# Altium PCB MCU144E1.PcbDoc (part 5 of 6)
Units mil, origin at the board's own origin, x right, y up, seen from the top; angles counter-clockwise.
Board outline 2755.9 x 2276.49 mil, 10 copper layers (Top Layer, L02_GND1, L03_SIG1, L04_GND2, L05_SIG2, L06_PWR, L07_GND3, L08_SIG3, L09_GND4, Bottom Layer), stack 60.4 mil thick; 257 components, 312 nets, 1297 pads, 831 vias.
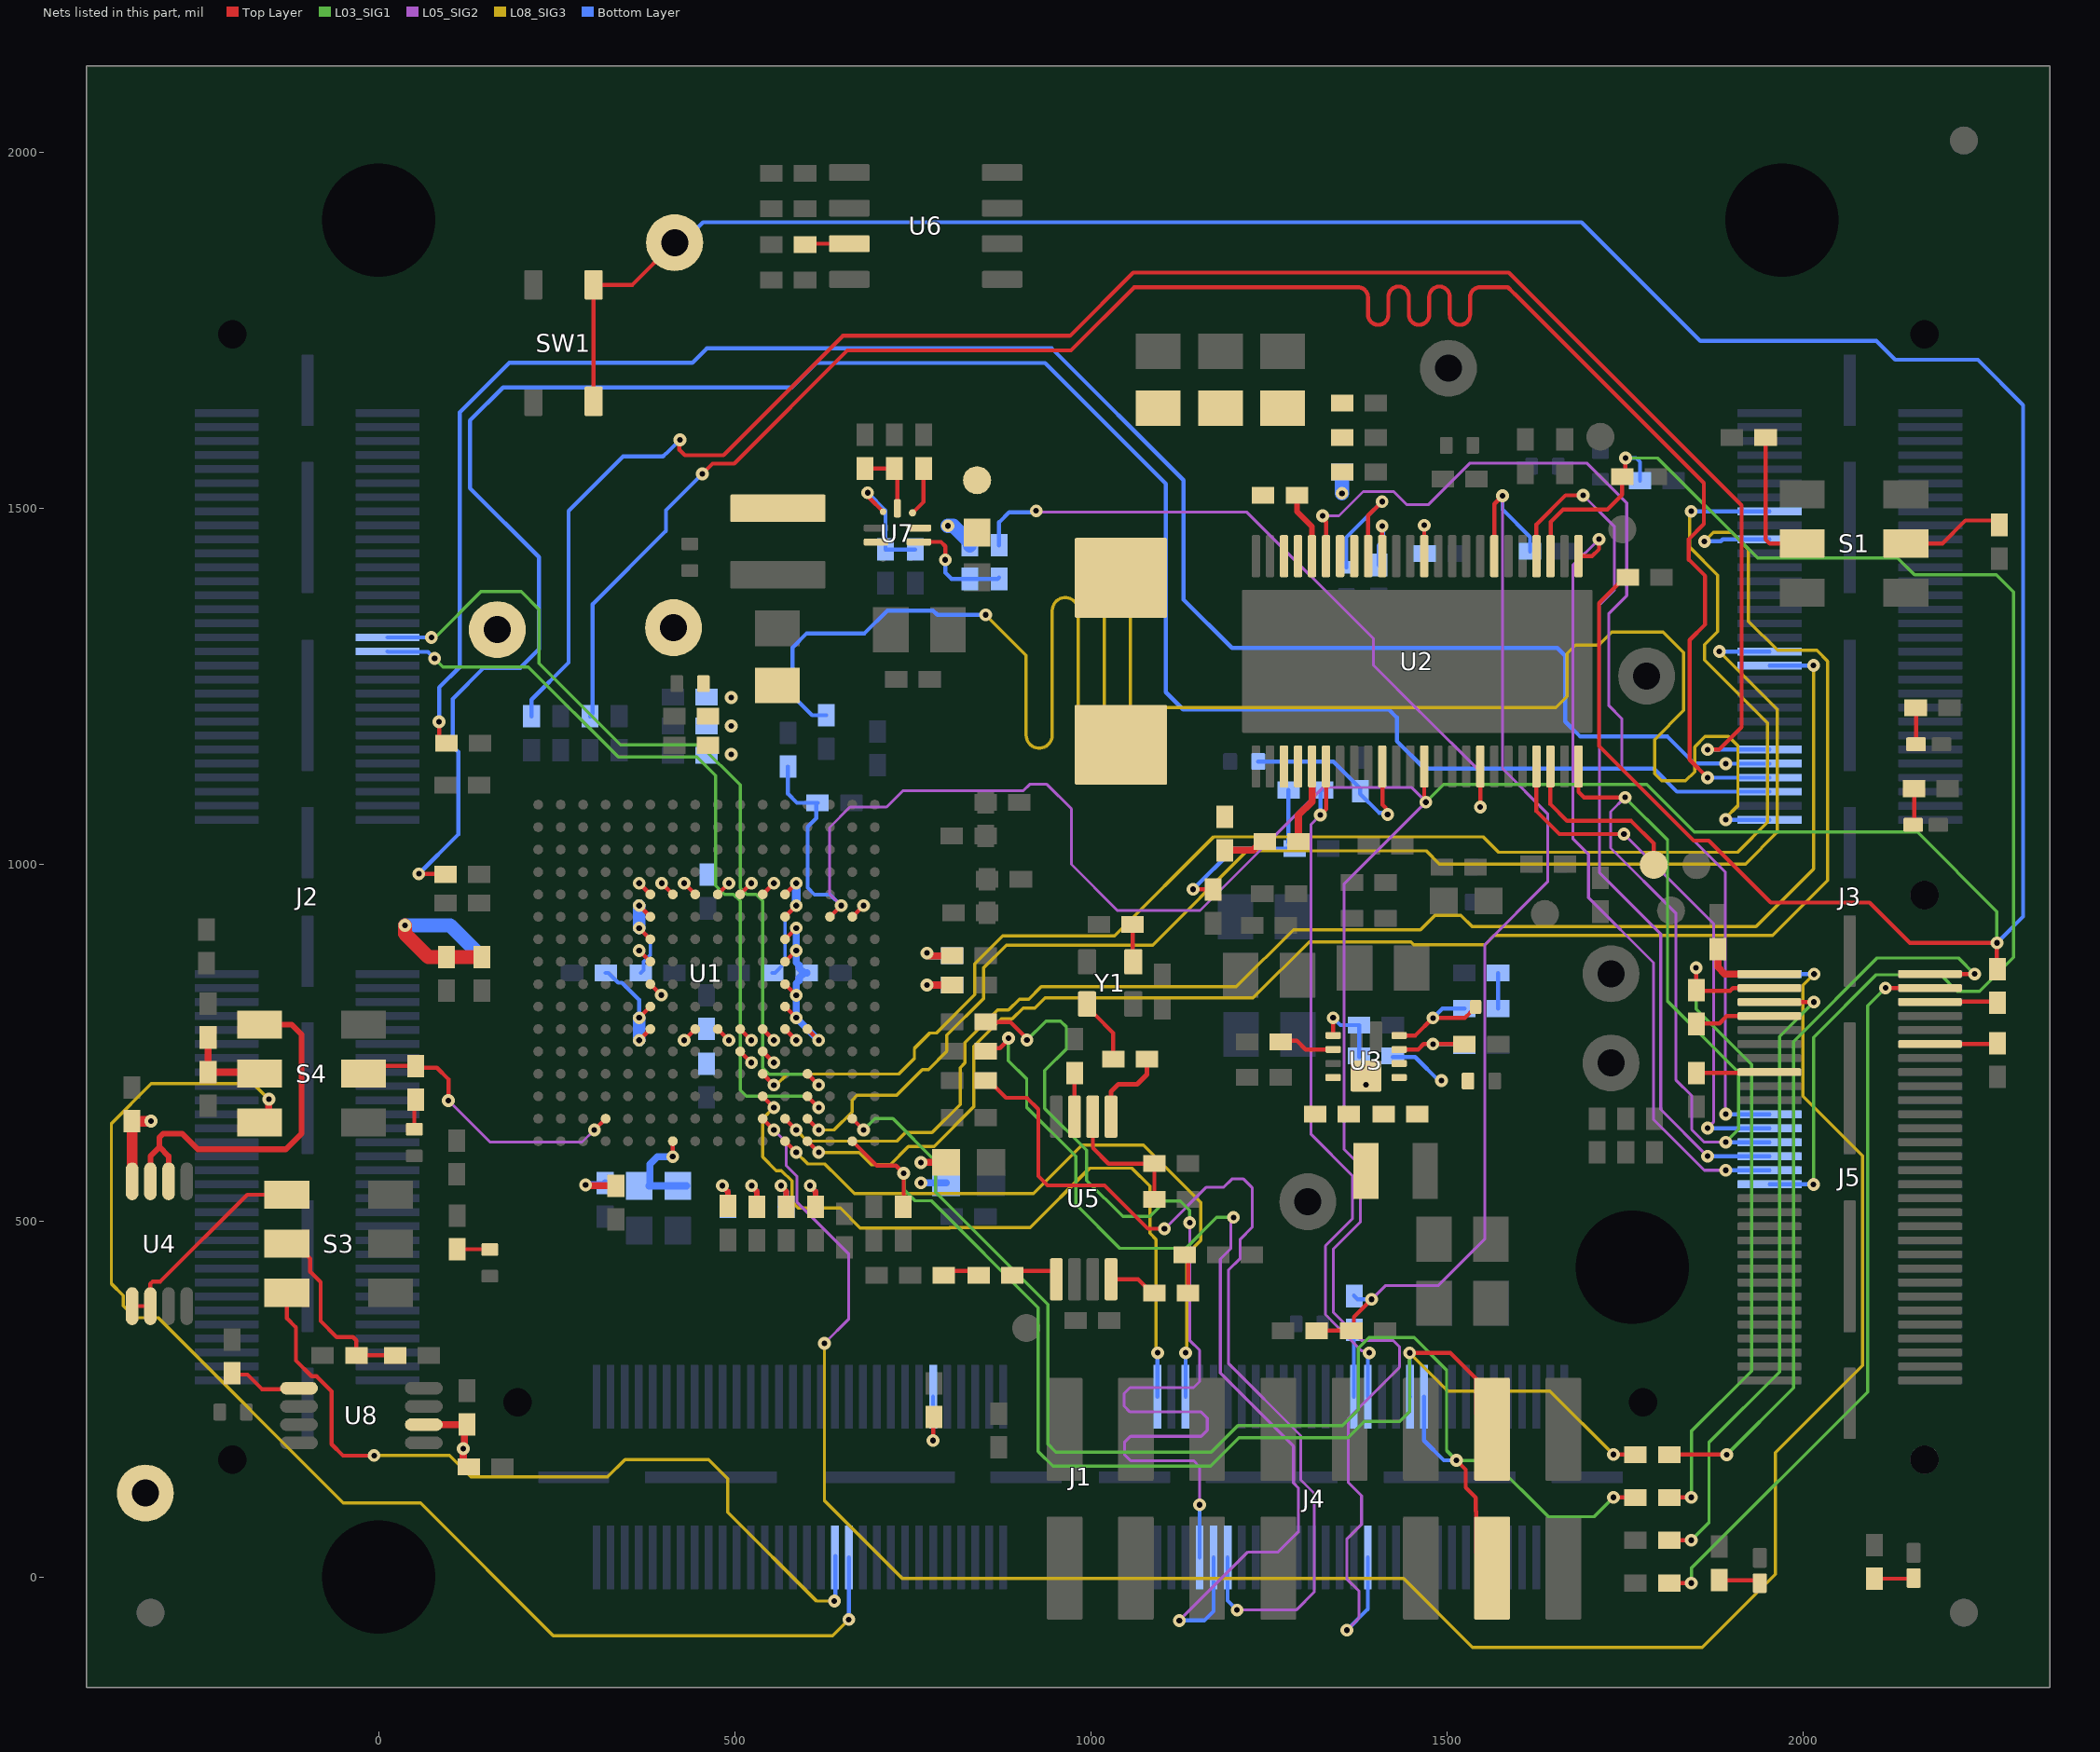
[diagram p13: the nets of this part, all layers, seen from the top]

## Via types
v1: diameter 18, hole 8, Top Layer to Bottom Layer, tented both sides, 777 vias
v2: diameter 19.68, hole 7.87, Top Layer to Bottom Layer, tented top, 54 vias

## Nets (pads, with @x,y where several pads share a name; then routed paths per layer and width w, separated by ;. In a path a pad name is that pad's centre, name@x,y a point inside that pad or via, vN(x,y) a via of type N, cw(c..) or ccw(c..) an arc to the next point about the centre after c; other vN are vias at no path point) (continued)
MCU_GPIO241: J3.105 U1.N11 | length 2233
  Top Layer w5.66: U1.N11@539,706.48 v1(554.75,690.73)
  L08_SIG3 w4.5: v1@556.92,692.91 v1(554.75,690.73) 558.08,690.73 573.61,706.27 730.27,706.27 752.02,728.02 752.02,742.21 773.6,763.79 782.94,763.79 836.86,817.71 836.86,860.77 859.76,883.68 876.13,900.04 1032.86,900.04 1172.08,1039.27 1550.59,1039.27 1572.16,1017.69 1907.67,1017.69 1949.82,1059.84 1949.82,1199.09 1861.33,1287.58 1861.33,1309.02 1879.79,1327.48 1879.79,1406.69 1840.28,1446.19 1840.28,1494.24 v1(1842.4,1496.36)
  Bottom Layer w5.66: v1(1842.4,1496.36) J3.105@1952.59,1496.36
MCU_GPIO242: J1.56 U1.T12 | length 957.1
  Top Layer w5.66: U1.T12@570.49,611.99 v1(586.24,596.24)
  L08_SIG3 w4.5: v1(586.24,596.24) 602.47,580.02 626.3,580.02 645.67,560.65 668.14,538.18 919.08,538.18 987.28,606.39 1073.61,606.39 1153.83,526.17 1153.83,472.69 1134.63,453.48 1134.63,316.64 v1(1132.83,314.84)
  Bottom Layer w5.66: J1.56@1132.74,253.19 1132.74,314.75 v1(1132.83,314.84)
MCU_GPIO243: J3.83 U1.R12 | length 2022.3
  Top Layer w5.66: U1.R12@570.49,643.49 v1(586.24,627.74)
  L08_SIG3 w4.5: v1(586.24,627.74) 602.01,611.97 ; 602.01,612.03 727.36,612.03 739.59,624.26 776.9,624.26 816.27,663.63 816.27,715.27 822.99,722 822.99,750.28 868.96,796.25 884.25,796.25 899.42,811.42 912.42,811.42 930,829 1204,829 1284,909 1462.56,909 1482.78,929.22 1519.36,929.22 1535.11,913.47 1933.59,913.47 2014.24,994.12 v1(2014.24,1279.91)
  Bottom Layer w5.66: J3.83@1952.59,1279.82 v1@2014.15,1279.82
MCU_GPIO244: J3.85 U1.R13 | length 1962.4
  Top Layer w5.66: U1.R13@601.99,643.49 v1(617.74,627.74)
  L08_SIG3 w4.5: v1(617.74,627.74) 639.39,627.74 664.55,652.89 664.55,669.25 671.53,676.23 727.04,676.23 727.24,676.43 763.22,712.42 771.84,712.42 797.74,738.32 797.74,760.74 849.49,812.48 849.49,855.54 881.36,887.42 1086.84,887.42 1219.02,1019.59 1470.46,1019.59 1489.02,1001.04 1918.69,1001.04 1963.59,1045.93 1963.59,1218.07 v1(1882.15,1299.51)
  Bottom Layer w5.66: v1(1882.15,1299.51) J3.85@1952.59,1299.51
MCU_GPIO245: J3.101 U1.T13 | length 2376.6
  Top Layer w5.66: U1.T13@601.99,611.99 v1(617.74,596.24)
  L08_SIG3 w4.5: v1(617.74,596.24) 674.48,596.24 691.62,579.11 718.12,579.11 743.53,604.52 779.72,604.52 835.62,660.41 835.62,745.05 874.19,783.62 889.48,783.62 904.65,798.8 921.33,798.8 935.53,813 1227.6,813 1306.47,891.87 1449.32,891.87 1453.14,888.05 1553.05,888.05 1565.84,900.84 1956.99,900.84 2034.2,978.05 2034.2,1285.85 2019.05,1301 1964,1301 1923,1342 1923,1442.92 1899.02,1466.89 1873.91,1466.89 v1(1861.2,1454.19)
  Bottom Layer w5.66: v1(1861.2,1454.19) 1884.07,1454.19 1886.87,1456.99 J3.101@1952.59,1456.99
MCU_GPIO246: J1.60 U1.P11 | length 1045.4
  Top Layer w5.66: U1.P11@539,674.98 v1(554.75,659.24)
  L08_SIG3 w4.5: v1(554.75,659.24) 538.96,643.45 538.96,589.8 558.27,570.5 565.38,570.5 580.05,555.83 580.05,526.95 589,518 648.36,518 676.08,490.28 801.44,490.28 801.64,490.48 914.43,490.48 998.05,574.1 1057.32,574.1 1082.75,548.67 1082.75,482.8 1091.54,474.01 1091.54,316.75 v1(1093.46,314.84)
  Bottom Layer w5.66: J1.60@1093.37,253.19 1093.37,314.75 v1(1093.46,314.84)
MCU_GPIO247: J3.59 U1.R11 | length 3059.9
  Top Layer w5.66: U1.R11@539,643.49 v1(554.75,627.74)
  L08_SIG3 w4.5: v1(625.8,328.2) 625.8,107.2 735,-2 1439,-2 1535.55,-98.55 1857.86,-98.55 1960.49,4.09 1960.49,174.49 2083,297 2083,591.46 1999.42,675.03 1999.42,830.98 v1(2015.08,846.63)
  L05_SIG2 w4: v1(554.75,627.74) 572.14,610.34 572.14,577.69 587.42,562.41 587.42,526.02 660,453.44 660,362.39 v1(625.8,328.2)
  Bottom Layer w5.66: J3.59@1952.59,846.63 v1(2015.08,846.63)
MCU_GPIO248: J2.35 U1.P13 | length 1138.8
  Top Layer w5.66: U1.P13@601.99,674.98 v1(617.74,659.24)
  L03_SIG1 w4.5: v1(78.53,1289.7) 90.25,1277.98 210.02,1277.98 336.64,1151.36 446.94,1151.36 472.86,1125.44 472.86,970.87 485.25,958.48 498.19,958.48 507.5,949.17 507.5,683.85 516.33,675.02 554.77,675.02 601.96,675.02 602.03,674.95 v1(617.74,659.24)
  Bottom Layer w5.66: J2.35@12.41,1299.59 13.01,1298.99 69.24,1298.99 v1(78.53,1289.7)
MCU_GPIO249: J2.33 U1.N13 | length 1207.1
  Top Layer w5.66: U1.N13@601.99,706.48 v1(617.74,690.73)
  L03_SIG1 w4.5: v1(74.06,1319.18) 79.18,1319.18 143.58,1383.58 199.97,1383.58 225,1358.55 225,1283 339.31,1168.69 450.84,1168.69 507.54,1111.99 507.54,967.69 516.74,958.48 526.97,958.48 527.04,958.41 529.76,958.41 538.96,949.21 538.96,715.29 548.21,706.04 602.43,706.04 v1(617.74,690.73)
  Bottom Layer w5.66: J2.33@12.41,1319.27 12.46,1319.23 74.02,1319.23 v1(74.06,1319.18)
MCU_TCK: J1.22 J4.4 R61.1 U1.R15 | length 2036.5
  Top Layer w5.66: U1.R15@664.98,643.49 v1(680.73,627.74) ; v1(1513.05,163.8) 1525.98,150.86 1525.98,125.51 1540.24,111.25 1540.24,92.42 1540.83,91.83 1540.83,34.73 J4.4@1563,12.56 ; v1(1733.37,111.85) R61.1@1764.41,111.85
  L03_SIG1 w4.5: v1(680.73,627.74) 696.73,643.74 721.79,643.74 722.08,643.45 781.67,583.85 781.67,540.21 939.25,382.64 939.25,186.75 950.82,175.18 1168.76,175.18 1206.13,212.56 1353.07,212.56 1375.37,234.87 1375.37,321.14 1390.42,336.18 1453.69,336.18 1499.18,290.69 1499.18,177.66 v1(1513.05,163.8) 1562.89,163.8 1641.96,84.73 1706.25,84.73 v1(1733.37,111.85)
  Bottom Layer w5.66: J1.22@1467.38,253.19 1467.38,191.66 1495.25,163.8 v1(1513.05,163.8)
MCU_TMS: J1.24 J4.3 R41.1 R60.1 U1.T15 | length 1894.4
  Top Layer w5.66: U1.T15@664.98,611.99 699.2,577.77 726.34,577.77 v1(737.09,567.02) 737.09,528.04 R41.1@728.93,519.88 ; v1(1447.24,314.71) 1504.42,314.71 1540.83,278.3 1540.83,229.61 J4.3@1563,207.44 ; v1(1733.37,172.01) R60.1@1764.41,172.01
  L03_SIG1 w4.5: v1(737.09,567.02) 737.09,544.47 753.23,528.33 775.7,528.33 925.8,378.23 925.8,176.34 946.69,155.45 1167.69,155.45 1207.84,195.61 1360.86,195.61 1383.55,218.29 1433.51,218.29 1447.24,232.03 v1(1447.24,314.71)
  L08_SIG3 w4.5: v1(1447.24,314.71) 1500.64,261.32 1644.06,261.32 v1(1733.37,172.01)
  Bottom Layer w5.66: v1(1447.24,314.71) 1447.47,314.48 1447.47,253.41 J1.24@1447.7,253.19
MCU_XRSn: C97.1 J1.29 R16.1 R46.1 R64.1 SW1.3 SW1.4 TP15.1 U1.F14 U2.13 | length 7972.6
  Top Layer w5.66: SW1.3@301.81,1650.94 SW1.4@301.81,1814.33 356.21,1814.33 TP15.1@415.49,1873.61 ; U1.F14@633.49,926.95 v1(649.23,942.7) ; U2.13@1467.78,1138.1 1467.78,1093.29 1470,1091.07 v1(1470,1088) ; R16.1@1753.45,1403.68 1749.51,1403.68 1713.21,1367.38 1713.21,1166.79 1846,1034 1867.15,1034 1954.16,946.99 2093.01,946.99 2149.53,890.47 v1(2271.66,890.47) 2271.66,854.3 R64.1@2272.29,853.67
  L03_SIG1 w4.5: v1(1470,1088) 1494.92,1112.92 1780.08,1112.92 1847,1046 2160,1046 2271.66,934.34 v1(2271.66,890.47)
  L05_SIG2 w4: v1(649.23,942.7) 633,958.94 633,1052.45 661.55,1081 712.99,1081 736.26,1104.27 905.27,1104.27 914,1113 938.12,1113 972.41,1078.7 972.41,1000.59 1037,936 1152.99,936 1325.39,1108.4 1450.34,1108.4 1470,1088.74 v1(1470,1088) 1355,973 1355,601 1377.88,578.12 1377.88,498.1 1340,460.22 1340,372 1380.11,331.89 1424.54,331.89 1433.14,323.29 1433.14,294.5 1360.86,222.22 1360.86,133.08 1379.8,114.15 1379.8,73.8 1359,53 1359,-2.52 1376.1,-19.62 1376.1,-57.49 v1(1359.05,-74.53)
  Bottom Layer w5: 602.31,1053.26 602.31,1048.47 602.24,1048.4 602.24,967.78 611.81,958.2 633.73,958.2 v1(649.23,942.7)
  Bottom Layer w5.66: TP15.1@415.49,1873.61 426.81,1873.61 455.44,1902.23 1688.68,1902.23 1855.21,1735.71 2102.29,1735.71 2128.9,1709.1 2244.9,1709.1 2308.52,1645.48 2308.52,927.33 v1(2271.66,890.47) ; R46.1@574.63,1138.09 574.63,1099.68 587.27,1087.04 C97.1@616.24,1087.04 614.44,1085.25 614.44,1065.39 602.31,1053.26 ; v1(1359.05,-74.53) 1388.64,-44.95 J1.29@1388.64,27.59
NetC38_1: C38.1 L4.2 U2.45 U2.46
NetC38_2: C38.2 U2.44 | length 94.5
  Top Layer w8: C38.2@1288.94,1519 1288.94,1496.06 1310.3,1474.7 U2.44@1310.3,1433.38
NetC39_1: C39.1 R7.1 | length 60.9
  Top Layer w10: R7.1@1188,1020.38 1227.64,1020.38 1239.9,1032.64 C39.1@1243.84,1032.64
NetC39_2: C39.2 U2.5 | length 113.4
  Top Layer w10: C39.2@1291.08,1032.64 1291.08,1069.43 1310.3,1088.65 U2.5@1310.3,1138.1
NetC40_1: C40.1 U3.10
NetC40_2: C40.2 L5.2 R12.2 U3.11
  other v2: 1386.22,691.5
NetC41_2: C41.2 U2.39 | length 100.9
  Top Layer w5.66: U2.39@1408.73,1433.38 v1(1408.73,1475.73) v1@1408.73,1476.73
  Bottom Layer w5.66: C41.2@1404,1421 1404,1448.51 1409.77,1454.29 1409.77,1474.68 v1(1408.73,1475.73)
NetC42_1: C42.1 U2.40 | length 198.1
  Top Layer w5.66: U2.40@1389.04,1433.38 1389.04,1490.31 v1(1408.73,1510)
  Bottom Layer w5.66: C42.1@1358.5,1417.46 1358.5,1459.77 v1(1408.73,1510)
NetC46_2: C46.2 R67.2 U3.2 | length 80.9
  Bottom Layer w5.66: R67.2@1423.62,730 1455,730 v1@1490,695
  other v1: 1492,697
NetC47_2: C47.2 R13.2 U3.4 | length 175
  Top Layer w5.66: U3.4@1432.48,760.39 1455.39,760.39 v1(1480,785) 1524.69,785 1533.04,793.35 1535.01,793.35 1540.05,798.39 C47.2@1540.05,800.36
  Bottom Layer w5.66: v1(1480,785) 1493.19,798.19 R13.2@1524.25,798.19
NetC51_1: C51.1 R13.1 | length 49.7
  Bottom Layer w5.66: R13.1@1571.5,798.19 C51.1@1571.5,847.93
NetC78_1: C78.1 R53.1 S3.5 | length 272.2
  Top Layer w5.66: S3.5@-128.83,468 -117.02,468 -96,446.98 -96,428.52 -81.49,414.01 -81.49,359.49 -59,337 -36,337 -31.28,332.28 R53.1@-31.28,311.26 23.24,311.26 C78.1@23.32,311.35
NetC80_2: C80.2 R56.1 | length 38.8
  Top Layer w5.66: R56.1@109.99,460.35 109.91,460.27 148,460.27 C80.2@148.43,459.84
NetC82_2: C82.2 R58.1 | length 42.5
  Top Layer w5.66: C82.2@50,628.7 50,668.38 R58.1@52,670.38
NetC87_1: C87.1 U8.5 | length 104.1
  Top Layer w5.66: C87.1@-206,286.38 -203.81,284.19 -184.19,284.19 -163.87,263.87 -113.15,263.87 U8.5@-111.81,265.2
NetC94_1: C94.1 R57.1 S4.5 | length 122
  Top Layer w10: R57.1@-239.39,757.62 C94.1@-239.39,708.87 -168.97,708.87 S4.5@-167,706.9
NetC96_1: C96.1 R70.2 U1.T7 | length 141.4
  Top Layer w5.66: v1(412.84,590.25) 412.84,611.82 U1.T7@413.01,611.99
  Bottom Layer w10: C96.1@379.51,549.31 R70.2@432.23,549.31 ; C96.1@380.77,549.31 380.77,579.74 391.27,590.25 v1(412.84,590.25)
NetJ1_32: J1.32 R74.1 | length 95.8
  Bottom Layer w5.66: R74.1@1368.76,348.9 1368.76,347.31 1368.96,347.11 J1.32@1368.96,253.19
NetJ1_72: J1.72 R79.1 | length 95
  Top Layer w5.66: v1(778.36,191.64) 778.36,223.76 R79.1@779.3,224.7
  Bottom Layer w5.66: J1.72@778.29,253.19 J1.72@778.29,253.19 778.33,191.68 v1(778.36,191.64)
NetL4_1: L4.1 R7.2 U2.3 U2.4
NetL7_1: L7.1 U7.2
NetLED1_1: LED1.1 R19.1 | length 58.7
  Top Layer w5.66: R19.1@1881.81,-4.5 1934.78,-4.5 LED1.1@1938.84,-8.55
NetLED2_1: LED2.1 R20.1 | length 55.4
  Top Layer w5.66: R20.1@2099.84,-2.34 2153.94,-2.34 LED2.1@2154.84,-1.43
NetLED3_1: LED3.1 R47.1 | length 56.6
  Top Layer w5.66: R47.1@2155.21,1106.99 2155.84,1106.36 LED3.1@2155.84,1050.61
NetLED4_1: LED4.1 R48.1 | length 56.6
  Top Layer w5.66: R48.1@2157.62,1220.57 2158.25,1219.94 LED4.1@2158.25,1164.19
NetR5_1: R5.1 R8.2 U2.10 | length 284.3
  Top Layer w5.66: U2.10@1409.09,1135 1409.09,1084.34 1414.02,1079.41 1414.02,1073.15 v1(1416.38,1070.79)
  Bottom Layer w5.66: R5.1@1234.68,1145 1340.36,1145 1377.92,1107.44 R8.2@1377.92,1103.5 1377.92,1099.56 1404.33,1073.15 1414.02,1073.15 v1(1416.38,1070.79)
NetR6_1: R6.1 R9.2 R66.2 | length 279.8
  Top Layer w5.66: v1(1143.39,965.62) R9.2@1171.09,965.62
  Bottom Layer w5.66: v1(1143.39,965.62) 1200.42,1022.65 R6.1@1285.94,1022.65 1277.2,1031.39 R66.2@1277.2,1105
NetR12_1: R12.1 U3.1
NetR14_1: R14.1 R18.2 U3.3 | length 139.2
  Top Layer w5.66: U3.3@1432.48,740.71 1459.24,740.71 1466.86,748.33 v1(1480,748.33) R14.1@1524.3,748.33
  Bottom Layer w5.66: v1(1480,748.33) R18.2@1524.25,748.33
NetR17_2: R17.2 U3.8 | length 79.4
  Top Layer w5.66: R17.2@1266.26,751.53 1267.73,753 1289,753 1301.29,740.71 U3.8@1339.96,740.71
NetR21_1: R21.1 R22.2 U7.5 | length 156.8
  Top Layer w5.66: U7.5@758.23,1453.27 789.41,1453.27 795.49,1447.19 v1@795.49,1427.33
  Bottom Layer w5.66: v1@795.49,1427.33 795.49,1410.11 804.22,1401.38 R21.1@830,1401.38 869.03,1401.38 R22.2@871,1403.35
  other v1: 795.49,1428.22
NetR28_2: R28.2 U7.7 | length 68.7
  Top Layer w5.66: U7.7@749.37,1494.11 765,1509.74 R28.2@765,1556.38
NetR30_1: R30.1 R33.2 U5.2 | length 189.5
  Top Layer w5.66: U5.2@1002.56,646.36 1002.56,602.44 1024.62,580.38 R30.1@1089.02,580.38 R33.2@1089.02,530.38
NetR34_1: R34.1 U5.3 | length 58.4
  Top Layer w5.66: U5.3@976.97,646.36 R34.1@976.97,704.79
NetR36_1: R36.1 Y1.3 | length 85.6
  Top Layer w5.66: Y1.3@1002.52,800.47 1002.52,791.75 1005.02,789.25 1005.75,789.25 1031.15,763.85 R36.1@1031.15,727.19
NetR36_2: R36.2 U5.1 | length 117
  Top Layer w6.66: U5.1@1028.15,646.36 1028.15,681.59 1038.34,691.78 1064.64,691.78 1078.39,705.54 R36.2@1078.39,727.19
NetR37_2: R37.2 Y1.1 | length 56.4
  Top Layer w5.66: R37.2@1058.39,912.19 1058.39,868.62 Y1.1@1067.48,859.53
NetR38_1: R38.1 U5.8 | length 68.7
  Top Layer w5.66: U5.8@1028.15,418.02 1066.08,418.02 1085.08,399.02 R38.1@1089.02,399.02
NetR42_1: R42.1 S1.2 | length 146.9
  Top Layer w5.66: S1.2@2144,1451.1 2195.19,1451.1 2227.47,1483.38 2268.86,1483.38 R42.1@2275,1477.24
NetR43_2: R43.2 S1.5 | length 196.5
  Top Layer w5.66: R43.2@1946.98,1599.64 1946.98,1456.83 1952.71,1451.1 S1.5@1998.33,1451.1
NetR58_2: R58.2 S4.2 U1.R4 | length 418.2
  Top Layer w5.66: S4.2@-21.33,706.9 -10.61,717.62 R58.2@52,717.62 ; R58.2@52.55,715.11 81.89,715.11 98,699 v1(98,669) ; v1(302.78,627.74) U1.R4@318.53,643.49
  L05_SIG2 w4: v1(98,669) 156.36,610.64 285.68,610.64 v1(302.78,627.74)
NetR67_1: R67.1 R68.2 U3.7 | length 138
  Top Layer w5.66: v1@1338.89,786.18 v1(1339.91,785.16) ; v1(1339.91,785.16) 1339.91,760.44 v1(1339.91,785.16)
  Bottom Layer w5.66: v1@1338.89,786.18 1350.07,775 R68.2@1376.38,775 R67.1@1376.38,730
NetR69_1: R69.1 U6.7 | length 62.1
  Top Layer w5.66: R69.1@598.62,1872 U6.7@660.72,1872
NetR71_2: R71.2 U2.36 | length 71.5
  Top Layer w5.66: U2.36@1467.78,1433.38 v1(1467.78,1476.73)
  Bottom Layer w5.66: 1467.78,1448.58 1467.78,1462.91 v1(1467.78,1476.73)
NetR73_1: R73.1 R76.2 U7.9 | length 167.6
  Top Layer w5.66: v1(686.43,1522.47) 688.79,1520.1 688.79,1515.08 U7.9@708.15,1495.71
  Bottom Layer w5.66: v1(686.43,1522.47) 711.5,1497.39 R73.1@711.5,1442.73 R76.2@753.23,1442.73
NetR75_1: R75.1 R78.2 U7.8 | length 98.6
  Top Layer w5.66: R75.1@683,1556.38 R78.2@724,1556.38 728.21,1552.17 U7.8@728.21,1500.51
NetR80_1: R80.1 U5.5 | length 70
  Top Layer w5.66: R80.1@889.52,429.69 945.35,429.69 951.38,423.66 U5.5@951.38,418.02
NetS3_6: S3.6 U4.1 U4.2 | length 300.3
  Top Layer w5.66: U4.1@-346,380.4 U4.2@-320.41,380.4 -320.41,411.68 -317.09,415 -306.47,415 -184.57,536.9 S3.6@-128.83,536.9
NetS4_6: S4.6 U4.6 U4.7 | length 543.5
  Top Layer w8: U4.7@-320.41,555.6 -320.41,590.81 -307.61,603.61 ; U4.6@-294.82,555.6 -294.82,590.81 -307.61,603.61 ; S4.6@-167,775.8 -122.23,775.8 -108.46,762.03 -108.46,622.46 -130.32,600.6 -253.8,600.6 -275.53,622.34 -302.66,622.34 -307.61,617.39 -307.61,603.61
nRESET: J5.6 R64.2 | length 84.9
  Top Layer w5.66: J5.6@2177.8,807.36 2178.43,808 R64.2@2262.43,808
PHY0_25MHZ_CLK: R32.2 R38.2 | length 60
  Top Layer w5.66: R38.2@1136.26,399.02 R32.2@1136.26,459.02
PHY1_25MHZ_CLK: R80.2 R97.2 | length 48.8
  Top Layer w5.66: R97.2@793.52,429.69 R80.2@842.28,429.69
PMIC_COMP1_IN+: J3.37 U2.21 | length 754.6
  Top Layer w5.66: U2.21@1625.26,1138.1 1625.26,1075.33 1657.48,1043.12 v1(1748.11,1043.12)
  L05_SIG2 w4: v1(1748.11,1043.12) 1873.77,917.46 1873.77,638.59 v1(1865.4,630.22)
  Bottom Layer w5.66: v1(1865.4,630.22) 1865.52,630.1 J3.37@1952.59,630.1
PMIC_COMP1_IN-: J3.35 U2.24 | length 1300.5
  Top Layer w5.66: U2.24@1684.32,1138.1 1684.32,1102.49 1692.2,1094.61 v1(1749.61,1094.61)
  L03_SIG1 w4.5: v1(1749.61,1094.61) 1809.3,1034.91 1809.3,808.46 1909.25,708.51 1909.25,628.82 v1(1890.94,610.5)
  L05_SIG2 w4: v1(1749.61,1094.61) 1729.56,1074.56 1729.56,1023.48 1820.78,932.27 1820.78,698.13 1843.26,675.65 1843.26,628.18 1860.94,610.5 v1(1890.94,610.5)
  Bottom Layer w5.66: v1(1890.94,610.5) 1891.03,610.41 J3.35@1952.59,610.41
PMIC_COMP2_IN+: J3.33 U2.28 | length 1234.9
  Top Layer w5.66: U2.28@1625.63,1430.28 1625.26,1430.64 U2.28@1625.26,1433.38 1625.26,1477.84 1666.14,1518.72 v1(1690.78,1518.72)
  L05_SIG2 w4: v1(1690.78,1518.72) 1734.85,1474.67 1734.85,1385.91 1713.94,1365 1713.94,988.74 1799.78,902.91 1799.78,656.47 v1(1865.4,590.85)
  Bottom Layer w5.66: v1(1865.4,590.85) 1865.52,590.73 J3.33@1952.59,590.73
PMIC_COMP2_IN-: J3.31 U2.25 | length 1116.2
  Top Layer w5.66: U2.25@1684.32,1433.38 1703.38,1433.38 1713.03,1443.03 v1(1713.03,1457.12)
  L05_SIG2 w4: v1(1713.03,1457.12) 1676.22,1420.31 1676.22,1036.78 1698.39,1014.61 1698.39,953.85 1789.58,862.66 1789.58,642.49 1860.94,571.13 v1(1890.94,571.13)
  Bottom Layer w5.66: v1(1890.94,571.13) 1891.03,571.04 J3.31@1952.59,571.04
PMIC_EN_OUT: R22.1 U2.17 | length 993.2
  Top Layer w5.66: v1(1546.52,1080.96) U2.17@1546.52,1138.1
  L05_SIG2 w4: v1@923,1495 1218.94,1495 1396.66,1317.28 1396.66,1279.93 1462.16,1214.42 1462.5,1214.42 1546.52,1130.39 v1(1546.52,1080.96)
  Bottom Layer w5.66: R22.1@871,1448.62 871,1481 885,1495 v1@923,1495
  other v1: 923,1497
PMIC_GPIO_1: TP7.1 U2.22 | length 250.9
  Top Layer w5.66: U2.22@1644.95,1138.1 1644.95,1085.05 1668.34,1061.66 1758.34,1061.66 1790,1030 TP7.1@1790,1000
PMIC_SAFE_OUT1: R1.1 R2.2 R15.1 R74.2 U2.31 | length 1615.6
  Top Layer w5.66: R2.2@1316.62,346 R1.1@1365.38,346 1369,349.62 1369,365 v1(1394,390) ; U2.31@1566.21,1433.38 1566.21,1506.76 v1(1577.62,1518.17)
  L05_SIG2 w4: v1(1394,390) 1413.1,409.1 1487.1,409.1 1553,475 1553,888 1641,976 1641,1071.71 1577.62,1135.09 v1(1577.62,1518.17)
  Bottom Layer w5.66: R74.2@1369,395.28 R74.2@1369.72,394.56 1374.28,390 v1(1394,390) ; v1(1577.62,1518.17) 1577.62,1499.09 1616.38,1460.34 R15.1@1616.38,1440
PMIC_SAFE_OUT2: J3.29 R10.1 R11.2 U2.27 | length 2020
  Top Layer w5.66: U2.27@1645.32,1430.28 1645.32,1481.4 1662.83,1498.92 1724.86,1498.92 1745.68,1519.73 R11.2@1745.68,1545 1750.26,1549.58 v1(1750.26,1571.15)
  L03_SIG1 w4.5: v1(1750.26,1571.15) 1795.24,1571.15 1935.77,1430.62 2132.41,1430.62 2156.03,1407 2271.04,1407 2294.99,1383.05 2294.99,869.99 2247.55,822.55 2215.92,822.55 2192.87,845.6 2102.14,845.6 2014.24,757.7 v1(2014.24,551.27)
  Bottom Layer w5.66: v1(1750.26,1571.15) 1765.3,1571.15 1770.74,1565.71 R10.1@1770.74,1539.37 ; J3.29@1952.59,551.36 2014.15,551.36 v1(2014.24,551.27)
PMIC_WAKE1: J1.30 R66.1 U2.6 | length 999.5
  Top Layer w5.66: v1(1322,1070) 1329.99,1077.99 U2.6@1329.99,1138.1
  L05_SIG2 w4: v1(1322,1070) 1309,1057 1309,621.4 1367,563.4 1367,503 1329,465 1329,368.55 1344.87,352.68 ; 1344.89,352.68 1380.16,317.42 1388.06,317.42 v1(1390.69,314.79)
  Bottom Layer w5.66: v1(1322,1070) 1322,1102.55 R66.1@1324.45,1105 ; J1.30@1388.64,253.19 v1@1388.64,314.75
PMIC_WAKE2: J3.39 U2.43 | length 1553.1
  Top Layer w5.66: v1(1325,1490) 1325,1486.66 1329.99,1481.67 U2.43@1329.99,1433.38
  L05_SIG2 w4: v1(1325,1490) 1348,1490 1382.1,1524.1 1425.06,1524.1 1443.67,1505.49 1473.49,1505.49 1532.1,1564.1 1695.9,1564.1 1752,1508 1752,1378 1727,1353 1727,1223.43 1745.14,1205.29 1745.14,1134.86 1890.56,989.44 1890.56,650.25 v1(1890.94,649.87)
  Bottom Layer w5.66: v1(1890.94,649.87) 1891.03,649.78 J3.39@1952.59,649.78
RTCK/EXTC: J5.7 R65.2 | length 107.3
  Top Layer w5.66: R65.2@1849.55,776.57 1850.35,777.36 1882.16,777.36 1892.47,787.68 J5.7@1952.2,787.68
SOM_GPIO6: J3.67 R88.1 | length 2819.1
  Top Layer w5.66: v1(454.33,1548.93) 468.74,1563.34 499.12,1563.34 657.94,1722.16 971.85,1722.16 1060.69,1811 1342.99,1811 1374.48,1811 cw(c1374.48,1796.67) 1388.81,1796.67 1388.81,1772.54 ccw(c1403.14,1772.54) 1417.47,1772.54 1417.47,1797.53 cw(c1431.8,1797.53) 1446.13,1797.53 1446.13,1772.51 ccw(c1460.46,1772.51) 1474.79,1772.51 1474.79,1797.51 cw(c1489.12,1797.51) 1503.45,1797.51 1503.45,1772.49 ccw(c1517.78,1772.49) 1532.11,1772.49 1532.11,1796.67 cw(c1546.44,1796.67) 1546.44,1811 1585.27,1811 1592.17,1804.1 1595,1801.27 1860.23,1536.04 1860.23,1478.44 1839.2,1457.4 1839.2,1428.39 1862.15,1405.43 1862.15,1337.6 1840.33,1315.78 1840.33,1147.53 v1(1865.4,1122.47)
  Bottom Layer w5.66: R88.1@296.63,1208.44 300.47,1212.29 300.47,1366.14 403.27,1468.94 403.27,1497.88 v1(454.33,1548.93) ; v1(1865.4,1122.47) 1865.52,1122.34 J3.67@1952.59,1122.34
SOM_GPIO7: J3.69 R94.1 | length 2747.3
  Top Layer w5.66: v1(84.89,1200.85) 84.89,1179.49 93.87,1170.51 R94.1@95.02,1170.51
  Bottom Layer w5.66: v1@84.89,1204.85 84.89,1248.94 113.79,1277.85 113.79,1635.28 183.52,1705 440.53,1705 460.53,1725 945,1725 1130,1540 1130,1372.22 1197.81,1304.41 1654.65,1304.41 1665.59,1293.47 1665.59,1201.29 1686.79,1180.09 1809.29,1180.09 1847.26,1142.12 v1(1890.94,1142.12) 1891.03,1142.03 J3.69@1952.59,1142.03
SOM_GPIO8: J3.71 R55.1 | length 2715.8
  Top Layer w5.66: v1@420.86,1594.8 422.19,1593.48 422.19,1582.71 429.89,1575 484.08,1575 651.74,1742.66 970.42,1742.66 1059.21,1831.45 1586.59,1831.45 1913.35,1504.69 1913.35,1193.35 1881.84,1161.84 v1(1865.4,1161.84)
  Bottom Layer w5.66: R55.1@214.63,1208.45 214.63,1231.84 266.71,1283.92 266.71,1496.99 343.15,1573.43 399.08,1573.43 402.76,1577.11 403.18,1577.11 v1(422.86,1596.8) ; v1(1865.4,1161.84) 1865.52,1161.71 J3.71@1952.59,1161.71
SOM_GPIO16: J3.65 R81.1 | length 3118.3
  Top Layer w5.66: v1(56.41,987.32) 93.05,987.32 R81.1@93.75,986.62
  Bottom Layer w5.66: v1(56.41,987.32) 111.7,1042.6 111.7,1158.6 104.02,1166.28 104.02,1232.98 147.59,1276.55 198.82,1276.55 225,1302.73 225,1432 128.27,1528.73 128.27,1624 174.58,1670.3 580.06,1670.3 614.26,1704.49 935.51,1704.49 1105,1535 1105,1242.5 1129.22,1218.28 1417.95,1218.28 1429.37,1206.86 1429.37,1173.73 1468.1,1135 1790.23,1135 1822.48,1102.75 1890.94,1102.75 1891.03,1102.66 J3.65@1952.59,1102.66
SOM_GPIO49: J1.53 R86.1 | length 1469.4
  Top Layer w5.66: R86.1@852.26,779.3 886.71,779.3 910,756.01 v1(910,754)
  L03_SIG1 w4.5: v1(910,754) 936.77,780.77 956.97,780.77 965.31,772.42 965.31,741.31 935.17,711.17 935.17,657.84 993.97,599.03 993.97,557.03 1044.56,506.44 1082.98,506.44 1104.44,527.91 1125.36,527.91 1138.52,514.74 v1(1138.52,497.65)
  L05_SIG2 w4: v1(1138.52,497.65) 1138.52,332.37 1152.42,318.47 1152.42,310.86 1152.42,274.56 1143.87,266.01 1054.75,266.01 1046.2,257.46 1046.2,240.36 1054.75,231.81 1154.68,231.81 1163.23,223.26 1163.23,206.16 1154.68,197.61 1055.41,197.61 1046.86,189.06 1046.86,171.96 1055.41,163.41 1143.87,163.41 1152.42,154.86 1152.42,136.75 v1(1152.42,101.47)
  Bottom Layer w5.66: J1.53@1152.42,27.59 v1(1152.42,101.47)
SOM_GPIO50: J1.51 R93.1 | length 1421.1
  Top Layer w5.66: R93.1@852.26,738.3 856.6,742.64 872,742.64 v1@886.08,756.72
  L03_SIG1 w4.5: v1(884.08,756.72) 884.08,724.9 909.73,699.25 909.73,659.69 978.76,590.66 978.76,523.29 1040.51,461.54 1132.99,461.54 1176.45,505 v1(1200,505)
  L05_SIG2 w4: v1(1124,-61) 1220.26,35.26 1262.86,35.26 1291,63.4 1291,125.39 1284.28,132.11 1284.28,183.73 1181.54,286.47 1181.54,446.54 1196,461 1196,501 v1(1200,505)
  Bottom Layer w5.66: v1(1124,-61) 1159.06,-61 1172.11,-47.95 J1.51@1172.11,27.59
SOM_GPIO51: J1.49 R52.1 | length 1379
  Top Layer w5.66: R52.1@852.26,697.3 856.19,697.3 865.17,688.32 880.61,672.86 909.9,672.86 926,656.76 926,563 939,550 1019,550 1080,489 v1(1103,489)
  L05_SIG2 w4: v1(1103,489) 1103.62,489 1162.1,547.48 1186.48,547.48 1197.86,558.86 1214.17,558.86 1226.2,546.82 1226.2,491.07 1209.5,474.37 1209.5,447.49 1192.8,430.79 1192.8,300.2 1294.48,198.52 1294.48,136.34 1313.46,117.36 1313.46,-20.95 1288.06,-46.35 v1(1205.03,-46.35)
  Bottom Layer w5.66: J1.49@1191.79,27.59 1191.79,-33.11 v1(1205.03,-46.35)
SOM_GPIO76: J3.61 R89.1 | length 2996.6
  L08_SIG3 w4.5: v1(852,1351) 908.95,1294.05 908.95,1182.11 ccw(c927.27,1182.11) 945.58,1182.11 945.58,1356.87 cw(c963.89,1356.87) 982.2,1356.87 982.2,1182.11 ccw(c1000.52,1182.11) 1018.83,1182.11 1018.83,1356.87 cw(c1037.14,1356.87) 1055.46,1356.87 1055.46,1182.11 ccw(c1073.77,1182.11) 1092.08,1182.11 1092.08,1211.3 1101.56,1220.78 1652.6,1220.78 1668.4,1236.58 1668.4,1296.54 1680.3,1308.45 1712.64,1308.45 1731.19,1327 1803,1327 1832,1298 1832,1216.73 1791.19,1175.91 1791.19,1127.81 1801.09,1117.91 1834.59,1117.91 1847.4,1130.71 1847.4,1165.5 1861.9,1180 1895,1180 1908.04,1166.96 1908.04,1083.04 1890.94,1065.94 v1(1890.94,1063.38)
  Bottom Layer w5.66: R89.1@628.5,1210.04 608.51,1210.04 581,1237.55 581,1305 601,1325 682,1325 714,1357 778.33,1357 784.33,1351 v1(852,1351) ; v1(1890.94,1063.38) 1890.98,1063.33 1952.54,1063.33 J3.61@1952.59,1063.29
TCK: J5.3 R61.2 R65.1 | length 978.2
  Top Layer w5.66: R61.2@1811.65,111.85 v1(1842.69,111.85) ; v1(1849.38,855.38) 1849.38,823.98 R65.1@1849.55,823.81 1850.41,822.95 1897.12,822.95 1901.22,827.05 J5.3@1952.2,827.05
  L03_SIG1 w4.5: v1(1842.69,111.85) 1842.69,204.53 1927.28,289.12 1927.28,719.72 1849.38,797.62 v1(1849.38,855.38)
TDI: J5.5 R63.2 | length 920.5
  Top Layer w5.66: R63.2@1811.65,51.69 v1(1842.69,51.69) ; J5.5@1952.2,807.36 v1(2014.74,807.36)
  L03_SIG1 w4.5: v1(1842.69,51.69) 1867.48,76.48 1867.48,188.94 1966.42,287.89 1966.42,759.05 v1(2014.74,807.36)
TDO: J5.4 R62.2 | length 1042
  Top Layer w5.66: R62.2@1811.65,-8.46 v1(1842.69,-8.46) ; v1(2115.26,827.05) J5.4@2177.8,827.05
  L03_SIG1 w4.5: v1(1842.69,-8.46) 1842.69,12.3 2090.21,259.82 2090.21,801.99 v1(2115.26,827.05)
TGT_PD: J5.15 R87.2 | length 103.1
  Top Layer w5.66: R87.2@1849.55,707.81 1951.08,707.81 J5.15@1952.2,708.94
TMS: J5.2 R60.2 | length 1074
  Top Layer w5.66: R60.2@1811.65,172.01 v1@1892.13,172.01 ; J5.2@2177.8,846.73 v1(2240.33,846.73)
  L03_SIG1 w4.5: v1(1892.4,171.74) 1986.15,265.48 1986.15,751.83 2103.43,869.12 2217.94,869.12 v1(2240.33,846.73)
VCC_6V0: C54.1 C55.1 C56.1 C57.1 C58.1 C59.1 C60.1 C66.1 R21.2 TP11.1 U2.41 U2.42 U7.6 | length 74.3
  Bottom Layer w20: v1(799,1476) 806.56,1476 830,1452.56 R21.2@830,1448.62 ; v1(1352.36,1521.64) C60.1@1352.36,1551.34
VDD_1V25: C2.2 C6.1 C7.1 C8.1 C9.1 C10.1 C11.1 C12.1 C15.1 L1.2 TP1.1 U1.E8 U1.E9 U1.E12 U1.F6 U1.F12 U1.G6 U1.L11 U1.L12 | length 427.1
  Top Layer w5.66: v1(365.77,911.2) U1.G6@381.52,895.46 ; v1(365.77,942.7) U1.F6@381.52,926.95 ; v1(428.76,974.2) U1.E8@444.51,958.45 ; U1.E9@476.01,958.45 v1(491.75,974.2) ; U1.L11@539,769.47 v1(554.75,753.72) ; U1.L12@570.49,769.47 v1(586.24,753.72) ; U1.F12@570.49,926.95 v1(586.24,942.7) ; U1.E12@570.49,958.45 v1(586.24,974.2)
  Bottom Layer w5: v1(365.77,911.2) 381.56,895.42 381.56,873.57 371.93,863.95 371.93,852.01 C10.1@368.14,848.21 ; C11.1@552.38,848.21 556.32,848.21 570.49,862.39 570.49,926.95 v1(586.24,942.7)
  Bottom Layer w12: v1(586.24,942.7) v1(586.24,974.2)
  Bottom Layer w18: v1(365.77,911.2) v1(365.77,942.7)
  other v1: 495,1155 495,1195 495,1235
VDDA_3V3: C3.1 C13.1 C14.1 C83.1 C84.1 C85.1 L2.2 TP14.1 U1.K6 U1.L6 U4.8 U8.2 | length 508.4
  Top Layer w5.66: v1(365.77,753.72) U1.L6@381.52,769.47 ; v1(365.77,785.22) U1.K6@381.52,800.97
  Top Layer w10: U8.2@63.39,214.02 123.84,214.02 C85.1@124.28,214.47 120.35,210.54 120.35,181.83 v1(118.82,180.3) C84.1@118.82,151.58 ; v1(290.53,550.61) 291.65,549.5 C3.1@333,549.5
  Top Layer w15: U4.8@-346,555.6 -346,639.6 C83.1@-346.41,640.01 v1(-319.6,640.01)
  Bottom Layer w5.66: C13.1@318.75,848.21 322.69,848.21 336.36,834.55 341.66,834.55 365.77,810.44 v1(365.77,785.22)
  Bottom Layer w10: v1(290.53,550.61) 315.2,550.61 C14.1@318,553.41 ; v1@761.42,553.68 L2.2@796.67,553.68
  Bottom Layer w18: v1(365.77,753.72) v1(365.77,785.22)
  other v1: 761.22,553.49
VDDIO_3V3: C16.1 C17.1 C18.1 C19.1 C20.1 C21.1 C22.1 C23.1 C24.1 C25.1 C26.1 C27.1 C76.1 C81.1 C88.1 C91.1 C92.2 C93.2 L3.2 TP2.1 U1.E6 U1.E7 U1.E10 U1.E11 U1.F15 U1.G12 U1.H6 U1.H12 U1.J6 U1.J12 U1.K12 U1.L8 U1.L9 U1.L10 U1.L13 U1.M10 U1.M11 | length 1260.5
  Top Layer w5.66: v1(365.77,879.71) U1.H6@381.52,863.96 ; v1(365.77,974.2) U1.E6@381.52,958.45 ; U1.J6@381.08,832.9 U1.J6@381.52,832.46 v1(396.83,817.15) ; v1(397.27,974.2) U1.E7@413.01,958.45 ; v1(428.76,753.72) U1.L8@444.51,769.47 ; U1.L9@476.01,769.47 v1(491.75,753.72) ; U1.M10@507.5,737.98 v1(523.25,722.23) ; U1.L10@507.5,769.47 v1(523.25,753.72) ; U1.E10@507.5,958.45 v1(523.25,974.2) ; U1.M11@539,737.98 v1(554.75,722.23) ; U1.E11@539,958.45 v1(554.75,974.2) ; U1.K12@570.49,800.97 v1(586.24,785.22) ; U1.J12@570.49,832.46 v1(586.24,816.72) ; U1.H12@570.49,863.96 v1(586.24,879.71) ; U1.G12@570.49,895.46 v1(586.24,911.2) ; U1.L13@601.99,769.47 v1(617.74,753.72) ; U1.F15@664.98,926.95 v1(680.73,942.7)
  Top Layer w8: v1(482.54,549.49) 482.54,548.97 490.16,541.36 C92.2@490.16,519.85 ; v1(523.54,549.49) 523.54,548.97 531.16,541.36 C24.1@531.16,519.85 ; v1(564.74,549.49) 564.74,548.97 572.35,541.36 C25.1@572.35,519.85 ; v1(605.74,549.49) 605.74,548.97 613.35,541.36 C76.1@613.35,519.85
  Top Layer w10: v1@761.42,582.23 L3.2@796.67,582.23 ; v1@769.76,831.3 C18.1@805.01,831.3 ; v1@769.76,872.3 C16.1@805.01,872.3
  Top Layer w20: v1(37,915) 37,903.21 69.67,870.54 C19.1@95.1,870.54 C21.1@144.93,870.53
  Bottom Layer w8: v1(482.54,549.49) 482.54,548.97 490.16,541.36 C22.1@490.16,519.85 ; v1(523.54,549.49) 523.54,548.97 531.16,541.36 C23.1@531.16,519.85 ; v1@564.54,549.49 564.54,548.97 572.16,541.36 C20.1@572.16,519.85 ; v1@605.54,549.52 605.54,549 613.16,541.38 C27.1@613.16,519.88
  Bottom Layer w10: C20.1@564.83,519.95 C20.1@564.93,519.85 ; v1(586.24,911.2) v1(586.24,879.71) 586.24,863.11 590.39,858.96 590.39,855.02 C88.1@597.2,848.21 ; C88.1@601.14,848.21 C88.1@597.2,848.21 ; v1(617.74,753.72) v1(586.24,785.22) v1(586.24,816.72) 586.24,833.32 590.39,837.46 590.39,841.4 C88.1@597.2,848.21 ; v1@769.76,831.3 C17.1@805.01,831.3 ; v1@769.76,872.3 C26.1@805.01,872.3
  Bottom Layer w20: v1(37,915) 100.47,915 C93.2@144.93,870.53
  other v1: 761.22,582.03 769.57,831.1 769.57,876.1
VREF_DEBUG: J5.1 R59.2 | length 101.6
  Top Layer w10: R59.2@1880.05,881.79 1880.05,856.32 1889.64,846.73 J5.1@1952.2,846.73
VREF_TRACE: J5.12 R85.2 | length 85.8
  Top Layer w5.66: J5.12@2177.8,748.31 2262.91,748.31 R85.2@2263.43,748.82
VREFHIAB: J1.85 S3.4 | length 1151.3
  Top Layer w5.66: S3.4@-128.83,399.1 -128.83,363.31 -116,350.47 -116,303.8 -94.09,281.89 -87.18,281.89 -66,260.71 -66,186.42 -50.05,170.48 -6.52,170.48 v1(-6.37,170.63)
  L08_SIG3 w4.5: v1(-6.37,170.63) 99.37,170.63 129.32,140.68 321.47,140.68 345.79,165 463,165 490,138 490,91 614.65,-33.65 v1(639.73,-33.65)
  Bottom Layer w5.66: v1(639.73,-33.65) 641.37,-32.02 J1.85@641.37,29.55
VREFHICDE: J1.83 S4.4 | length 1861.4
  Top Layer w10: S4.4@-167,638 -154.19,650.81 v1(-154.19,670.91)
  L08_SIG3 w4.5: v1(-154.19,670.91) -176.28,693 -319,693 -375.16,636.84 -375.16,411.87 -358.52,395.23 -358.52,380.75 -341.88,364.11 -309.59,364.11 -49.48,104 58.92,104 245.08,-82.16 637.49,-82.16 v1(659.99,-59.66)
  Bottom Layer w5.66: v1(659.99,-59.66) 660.11,-59.54 J1.83@660.11,27.53
pads on no net: FID1.1 FID2.1 FID3.1 FID4.1 FID5.1 FID6.1 J1.26 J1.27 J1.47 J1.79 J1.80 J1.81 J1.82 J1.84 J1.86 J1.87 J1.88 J1.MH1 J1.MH2 J2.1 J2.2 J2.3 J2.4 J2.5 J2.6 J2.7 J2.8 J2.9 J2.10 J2.11 J2.12 J2.13 J2.14 J2.15 J2.16 J2.17 J2.18 J2.19 J2.20 J2.22 J2.24 J2.37 J2.38 J2.39 J2.40 J2.41 J2.42 J2.43 J2.44 J2.45 J2.47 J2.49 J2.51 J2.61 J2.62 J2.63 J2.64 J2.65 J2.66 J2.67 J2.68 J2.69 J2.70 J2.71 J2.72 J2.73 J2.74 J2.75 J2.76 J2.77 J2.78 J2.79 J2.80 J2.81 J2.82 J2.83 J2.84 J2.85 J2.86 J2.87 J2.88 J2.89 J2.90 J2.91 J2.92 J2.93 J2.94 J2.95 J2.96 J2.101 J2.102 J2.MH1 J2.MH2 J3.1 J3.2 J3.3 J3.4 J3.5 J3.6 J3.7 J3.8 J3.9 J3.10 J3.11 J3.12 J3.13 J3.14 J3.15 J3.16 J3.17 J3.18 J3.19 J3.20 J3.21 J3.22 J3.23 J3.24 J3.25 J3.26 J3.28 J3.30 J3.32 J3.34 J3.36 J3.38 J3.40 J3.41 J3.42 J3.43 J3.44 J3.45 J3.46 J3.47 J3.48 J3.49 J3.50 J3.51 J3.52 J3.53 J3.54 J3.55 J3.56 J3.57 J3.58 J3.60 J3.62 J3.64 J3.66 J3.68 J3.70 J3.72 J3.73 J3.74 J3.75 J3.77 J3.79 J3.81 J3.86 J3.98 J3.110 J3.MH1 J3.MH2 J5. J5.8 J5.9 J5.10 J5.11 J5.13 J5.16 J5.17 J5.19 J5.20 J5.21 J5.22 J5.23 J5.24 J5.25 J5.26 J5.27 J5.28 J5.29 J5.30 J5.31 J5.32 J5.33 J5.34 J5.35 J5.36 J5.41 J5.42 J5.43 J5.44 J5.45 J5.46 J5.47 J5.48 J5.49 J5.50 J5.51 J5.52 J5.53 J5.54 J5.55 J5.56 J5.57 J5.58 MH1.1 MH2.1 MH3.1 MH4.1 U1.M12 U2.19 U3.0 U5.7 U7.1 U8.1 U8.3 U8.7 U8.8

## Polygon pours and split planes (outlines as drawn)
GND on L06_PWR "NONET_L-01_P-001" (solid, remove dead copper, pour order 94): -410,2121.49 -410,-155 2345.9,-155 2345.9,2121.49
3V3_OUT on L06_PWR "3V3_OUT_L06_P093" (solid, remove dead copper, pour order 93): 206.85,2066 567,2066 652,1981 652,1864 712,1804 1737,1804 1916.32,1624.68 2240.45,1624.68 2283,1582.13 2283,112 2169,-2 1669.79,-2 1599.68,68.11 1599.68,193.8 1510.1,283.38 1293.36,283.38 1275.49,300.45 1275.49,496.5 1274.66,497.33 1277.81,570.19 1256.42,591.58 1199.28,591.58 1178.7,571 1123.51,571 1032.53,480.02 1032.53,366.27 1012.3,346.05 1012.3,321.6 1001.32,310.62 916.64,310.62 863.23,364.03 863.23,1286.77 560,1590 331.46,1590 148.22,1773.24 148.22,2007.37
VDDA_3V3 on L06_PWR "VDDA_3V3_L06_P059" (solid, remove dead copper, pour order 59): 161.83,114.82 -150.17,114.82 -195.47,69.53 -358.53,69.53 -379,90 -379,197 -335,241 -335,588 -335,756 -284.27,806.73 404.83,806.73 418.36,793.2 418.36,558.03 451,525.39 704.04,525.39 722.62,543.98 722.62,568 727.18,572.56 801.16,572.56 823.61,550.11 823.61,424.27 789.34,390 333,390 286,343 286,239
VDD_1V25 on L06_PWR "VDD_1V25_L06_P037" (solid, remove dead copper, pour order 37): 574.89,674.25 576.9,672.24 703.2,672.24 708.97,678.01 708.97,901.51 686.61,923.87 671.13,923.87 658.44,936.56 658.44,1296.56 581.72,1373.28 364.19,1373.28 349.78,1357.26 315.78,1323.26 315.78,1207.24 418.51,1104.51 418.51,954.67 416.08,952.23 361.7,952.23 356.14,946.68 356.14,904.15 359.19,901.11 500.03,901.11 503.37,904.45 503.37,989.16 511.24,997.03 562.82,997.03 576.47,983.37 576.47,939.69 586.04,930.12 601.28,930.12 607.16,924.24 607.16,807.08 645.84,768.41 645.84,750.33 627.01,731.5 608.47,731.5 595.71,744.26 595.71,762.17 591.49,766.39 549.5,766.39 543.39,760.28 543.39,747.17 549.5,741.06 564.14,741.06 574.89,730.31
VDDIO_3V3 on L06_PWR "VDDIO_3V3_L06_P038" (solid, remove dead copper, pour order 38): 69,1310.67 69,1008 23,962 23,913.88 95.74,841.14 144.41,841.14 178.81,806.73 404.83,806.73 418.36,793.2 418.36,555.8 448.74,526.62 705.27,526.62 718.07,539.42 718.07,563.45 727.18,572.56 764.85,572.56 830,637.7 830,976.9 809.13,997.77 672.81,997.77 665,989.96 665,945.32 724.1,886.22 724.1,678.01 718,671.9 577.23,671.9 574.89,674.25 574.89,730.31 564.14,741.06 549.5,741.06 543.39,747.17 543.39,760.28 550.92,767.81 590.07,767.81 599.35,758.52 599.35,740.61 608.47,731.5 627.01,731.5 645.84,750.33 645.84,767.26 637.57,775.54 603.01,775.54 596.82,781.73 596.82,919.34 576.47,939.69 576.47,983.37 562.82,997.03 511.24,997.03 503.37,989.16 503.37,904.45 488.92,890 349.05,890 345.42,893.32 345.42,960.33 350.04,964.94 410.44,964.94 418.51,973.01 418.51,1104.51 297.02,1226.01 297.02,1356.05 276.45,1376.62 134.94,1376.62
5V0_OUT_CAN on L06_PWR "TOP_LAYER_NONET_P-001" (solid, remove dead copper, pour order 29): 1302.4,385.47 1318.87,369 1435,369 1570,504 1570,590 1626,646 1626,708 1701,783 1769.68,783 1799.78,813.1 1799.78,889.08 1791.66,897.21 1645.64,897.21 1557.76,809.33 1557.76,661.76 1328,432 1302.4,406.4
GND on Top Layer "NONET_L-01_P-001" (solid, remove dead copper, pour order 95): -398.96,2142.63 -398.96,-133.86 2356.94,-133.86 2356.94,2142.63
5V0_OUT_CAN on Top Layer "TOP_LAYER_NONET_P-001" (solid, remove dead copper, pour order 92): 1577.75,965.84 1575.65,967.93 1540.44,967.93 1538.38,965.87 1538.38,921.99 1553.78,906.58 1566.72,906.58 1672.44,800.86 1759.86,800.86 1772,813 1772,866 1748.21,889.79 1631.21,889.79 1577.75,943.25
GND on Top Layer "TOP_LAYER_NONET_P-001" (solid, remove dead copper, pour order 86): 1095,1773 1208,1773 1234.88,1746.12 1300.53,1746.12 1309.38,1737.27 1309.38,1704.97 1300.53,1696.12 1063.93,1696.12 1055.04,1705 1055.04,1738.52 1089.52,1773
GND on Top Layer "TOP_LAYER_NONET_P-001" (solid, remove dead copper, pour order 84): 1383.86,1660.16 1383.86,1539.52 1415.36,1539.52 1421.38,1545.55 1421,1545.94 1421,1600.29 1436.28,1615.56 1511.01,1615.56 1525.25,1600.83 1525.25,1530 1530.25,1525 1551.75,1525 1557,1530.25 1557,1578 1560.5,1581.5 1676.81,1581.5 1679,1583.69 1679,1620 1652,1647 1476,1647 1443,1680 1403.7,1680
GND on Bottom Layer "NONET_L-01_P-001" (solid, remove dead copper, pour order 96): -410,2121.49 -410,-155 2345.9,-155 2345.9,2121.49
GND on Bottom Layer "TOP_LAYER_NONET_P-001" (solid, remove dead copper, pour order 82): 1383.86,1539.52 1415.36,1539.52 1427.41,1551.58 1427.41,1583.08 1445.15,1600.81 1627.81,1600.81 1647.01,1581.61 1647.01,1544.81 1652,1539.82 1661.82,1539.82 1664.73,1542.73 1664.73,1566.73 1668.41,1570.41 1725.43,1570.41 1726.81,1571.79 1726.81,1598.8 1713.61,1612 1678.63,1612 1637.63,1653 1470,1653 1433,1690 1401,1690 1381,1670 1381,1542.38
GND on Bottom Layer "TOP_LAYER_NONET_P-001" (solid, remove dead copper, pour order 80): 1536.92,352.87 1608.87,352.87 1619,363 1619,524 1609,534 1588,534 1576.45,522.45 1576.45,442.87 1559.95,426.37 1547.29,426.37 1529.54,408.19 1529.54,360.26
GND on L02_GND1 "NONET_L-01_P-001" (solid, remove dead copper, pour order 60): -410,2121.49 -410,-155 2345.9,-155 2345.9,2121.49
GND on L04_GND2 "NONET_L-01_P-001" (solid, remove dead copper, pour order 68): -410,2121.49 -410,-155 2345.9,-155 2345.9,2121.49
GND on L09_GND4 "NONET_L-01_P-001" (solid, remove dead copper, pour order 70): -410,2121.49 -410,-155 2345.9,-155 2345.9,2121.49
GND on L07_GND3 "GND_L07_P074" (solid, remove dead copper, pour order 74): -410,2121.49 -410,-155 2345.9,-155 2345.9,2121.49
GND on L03_SIG1 "NONET_L-01_P-001" (solid, remove dead copper, pour order 64): -428.64,2160.2 -428.64,-180 2327.26,-180 2327.26,2160.2
GND on L08_SIG3 "NONET_L-01_P-001" (solid, remove dead copper, pour order 66): -410,2121.49 -410,-155 2345.9,-155 2345.9,2121.49
GND on L05_SIG2 "NONET_L-01_P-001" (solid, remove dead copper, pour order 65): -410,2121.49 -410,-155 2345.9,-155 2345.9,2121.49

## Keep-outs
Keep-Out Layer:
  circle w10: c-205.12,165.04 r40
  circle w10: c-205.12,1744.96 r40
  circle w10: c2170.12,957.56 r40
  circle w10: c2170.12,1744.96 r40
  circle w10: c2170.12,165.04 r40
  circle w10: c1774.96,245.12 r40
  circle w10: c195.04,245.12 r40
  circle w10: c0,0 r150
  circle w10: c0,1905 r150
  circle w10: c1970,1905 r150
  circle w10: c1760,435 r128

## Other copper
Top Layer:
  pour cut-out: 1024.04,1966.76 1043.76,1986.48 1710.17,1986.48 1763.29,1933.36 1763.29,1748.29 1724.49,1709.49 1598.4,1835.59 1598.4,1837.2 1049.34,1837.2 1027.05,1814.91 1017.67,1814.91
  region net GND: 371,1277 371,1266 399.27,1237.73 399.27,1155.98 427.15,1155.98 427.15,1258.89 417.35,1268.69 396.31,1268.69 385,1280 374,1280
  region net VDD_1V25: 524,1145 552.09,1173.09 552.09,1216.38 562.73,1227.01 591.16,1227.01 591.16,1276.84 582.39,1285.62 519.38,1285.62 432.23,1372.77 388.36,1372.77 373.92,1358.33 373.92,1312.35 400.65,1285.62 427.63,1285.62 444.51,1268.74 444.51,1153.79 453.3,1145
  region net NetC46_2: 1421.65,724.79 1421.65,717.26 1422.81,716.1 1457.74,716.1 1489.14,684.71 1536.13,684.71 1538.08,686.66 1538.08,706.38 1536.13,708.33 1491.67,708.33 1474.06,725.94 1422.81,725.94
  region net NetR12_1: 1459.11,637.61 1473.01,637.61 1473.59,638.19 1473.59,674.01 1441.34,706.26 1422.81,706.26 1421.08,704.53 1421.08,696.99 1442.08,675.99 1442.08,638.2 1442.67,637.61
  region net NetC40_2: 1403.94,615.78 1426.35,638.19 1426.35,664.45 1407.87,682.92 1407.87,722.8 1405.71,724.96 1386.22,724.96 1366.73,724.96 1364.57,722.8 1364.57,682.92 1346.09,664.45 1346.09,638.19 1368.5,615.78 1368.5,530.63 1403.94,530.63
  region net NetC40_1: 1313.33,637.61 1299.43,637.61 1298.85,638.19 1298.85,674.01 1331.1,706.26 1349.63,706.26 1351.36,704.53 1351.36,696.99 1330.36,675.99 1330.36,638.2 1329.77,637.61
  region net VCC_6V0: 821.3,1446.81 870.9,1446.81 885,1460.91 885,1484.24 983.76,1583 1293.14,1583 1343.77,1532.37 1343.77,1405.8 1345.72,1403.85 1353.63,1403.85 1355.58,1405.8 1355.58,1467.21 1357.62,1469.25 1361.42,1469.25 1363.45,1467.21 1363.45,1405.8 1365.4,1403.85 1373.31,1403.85 1375.26,1405.8 1375.26,1653.01 1356.19,1672.09 902.09,1672.09 810,1580 810,1505 782.87,1477.87 742.97,1477.87 742.97,1468.03 800.08,1468.03
  region net NetL7_1: 592.97,1475.04 499.18,1475.04 493.22,1481 491.52,1482.7 491.52,1517.87 493.44,1519.8 623.66,1519.8 625.37,1518.09 625.37,1496.41 663.59,1458.19 713.85,1458.19 715.41,1456.63 715.41,1450.31 713.45,1448.35 619.66,1448.35
  region net NetL4_1: 1044.87,1054 1036.87,1054 977.04,1113.83 977.04,1222.47 979.28,1224.72 1105.65,1224.72 1106.96,1223.4 1106.96,1114.76 1136.57,1085.14 1203.86,1085.14 1250.14,1085.14 1265.39,1100.39 1265.39,1165.31 1265.03,1165.68 1266.97,1167.63 1294.57,1167.63 1296.39,1165.81 1296.39,1093.13 1277.83,1074.56 1257.27,1054
  region net NetC38_1: 1054.7,1534.62 977.04,1456.95 977.04,1349.01 979.28,1346.76 1105.65,1346.76 1107.29,1348.4 1107.29,1457.05 1130.37,1480.13 1251,1480.13 1265.25,1465.88 1265.25,1402.84 1267.34,1400.75 1295.28,1400.75 1296.52,1401.99 1296.52,1467.69 1262.92,1501.29 1262.92,1525.33 1253.64,1534.62
  region net GND: 1578.49,775 1620,775 1630,765 1630,727.5 1622.5,720 1567.47,720 1555.8,708.33 1555.8,625.8 1536.67,606.67 1536.67,352.87 1542.92,346.62 1611.62,346.62 1615,350 1615,530 1681.05,596.05 1681.05,769.45 1565.5,885 1475,885 1455,905 1455,1035.79 1452.67,1038.13 1421.17,1038.13 1421.17,1024.12 1420.72,1023.66 1420.72,1009.65 1397.87,986.81 1397.87,903.63 1425,876.5 1425,812.43 1391.14,778.57 1391.14,738.28 1392.65,736.77 1407.35,736.77 1408.86,738.28 1408.86,777.51 1411.35,780 1450,780 1475,805 1490,805 1515,830 1540,830 1559.27,810.73 1559.27,794.22
  region net GND: 1157.21,934.67 1157.21,704.67 1172.17,689.71 1234.76,689.71 1234.76,895.83 1242.13,903.19 1242.13,935.88 1256.66,950.41 1256.66,972.91 1253.07,976.49 1229.71,976.49 1190.97,937.76 1160.3,937.76
  region net 5V0_IN: 1250.51,681.84 1240,671.33 1240,505 1302,443 1367,443 1470,340 1505,340 1521.38,356.38 1521.38,613.62 1518.19,616.81 1451.81,616.81 1445,610 1445,530 1420,505 1355,505 1327.92,532.08 1327.92,572.08 1295,605 1283.45,616.55 1283.45,687.88 1311.1,715.53 1311.1,716.1 1349.63,716.1 1350.79,717.26 1350.79,724.79 1349.63,725.94 1294.62,725.94 1282.01,713.34 1255.43,713.34 1250.51,708.41
  region net 3V3_OUT: 1424.82,1400.75 1422.87,1402.7 1422.87,1466.34 1425.69,1469.16 1425.69,1490.69 1450,1515 1450,1590 1460.81,1600.81 1505.59,1600.81 1509.5,1596.89 1509.5,1530 1485.18,1505.68 1473.39,1505.68 1451.44,1483.73 1451.44,1468.8 1454,1466.23 1454,1402.33 1452.42,1400.75
  region net 3V3_OUT: 836.04,494.17 836.04,650.63 842.95,657.54 887.46,657.54 905,640 905,500 895,490 840.21,490
  region net +12V0: 1405.42,1014.5 1405.42,1038.13 1395.32,1048.23 1395.32,1106.38 1394.63,1107.07 1394.63,1166 1393,1167.63 1347.24,1167.63 1344.13,1164.53 1344.13,1067.27 1316.66,1039.79 1316.66,1014.08 1271.95,969.37 1271.95,944.08 1257.87,930 1257.87,808.13 1261.2,804.8 1347.43,804.8 1357.11,795.13 1357.11,777.89 1363.07,771.93 1363.07,739.85 1366.15,736.77 1378.73,736.77 1381.37,739.41 1381.37,790.22 1395,803.85 1395,876.5 1382.5,889 1382.5,992.31 1383.23,992.31
  region net +1V25: 481.5,1426.5 670.11,1426.5 682.12,1438.5 713.45,1438.5 723.31,1428.64 723.31,1388.19 750,1361.5 750,1279.96 742.26,1272.22 742.26,1248.6 680.4,1248.6 621,1308 524.42,1308 439.54,1392.87 417.55,1392.87 410.82,1399.61 410.82,1416.96 420.35,1426.5
  pour cut-out: 469.86,1542.44 469.86,1365.28 647.03,1365.28 647.03,1542.44
  pour cut-out: 1364.45,617.24 1364.45,522.76 1490.66,522.76 1490.66,617.24
  pour cut-out: 903.51,1433.38 1179.8,1433.38 1179.8,1138.1 903.51,1138.1
  text ".Layer_Name" at -156.04,-2488.76 h60
L02_GND1:
  text ".Layer_Name" at -182.32,-2497.53 h60
L03_SIG1:
  pour cut-out: 2065,1083.23 cw(c2065,1095.23) 2053,1095.23 cw(c2065,1095.23) 2065,1107.23 cw(c2065,1095.23) 2077,1095.23 cw(c2065,1095.23)
  pour cut-out: 1011.15,926.85 cw(c1011.15,938.85) 999.15,938.85 cw(c1011.15,938.85) 1011.15,950.85 cw(c1011.15,938.85) 1023.15,938.85 cw(c1011.15,938.85)
  pour cut-out: 1605.59,360.4 cw(c1605.59,372.4) 1593.59,372.4 cw(c1605.59,372.4) 1605.59,384.4 cw(c1605.59,372.4) 1617.59,372.4 cw(c1605.59,372.4)
  pour cut-out: 1506.84,70.74 cw(c1506.84,82.74) 1494.84,82.74 cw(c1506.84,82.74) 1506.84,94.74 cw(c1506.84,82.74) 1518.84,82.74 cw(c1506.84,82.74)
  pour cut-out: 1615,128 cw(c1615,140) 1603,140 cw(c1615,140) 1615,152 cw(c1615,140) 1627,140 cw(c1615,140)
  pour cut-out: 1315,128 cw(c1315,140) 1303,140 cw(c1315,140) 1315,152 cw(c1315,140) 1327,140 cw(c1315,140)
  pour cut-out: 1115,128 cw(c1115,140) 1103,140 cw(c1115,140) 1115,152 cw(c1115,140) 1127,140 cw(c1115,140)
  pour cut-out: 1276.6,373.55 cw(c1276.6,385.55) 1264.6,385.55 cw(c1276.6,385.55) 1276.6,397.55 cw(c1276.6,385.55) 1288.6,385.55 cw(c1276.6,385.55)
  pour cut-out: 1025.56,315.1 cw(c1025.56,327.1) 1013.56,327.1 cw(c1025.56,327.1) 1025.56,339.1 cw(c1025.56,327.1) 1037.56,327.1 cw(c1025.56,327.1)
  pour cut-out: 712.23,584.24 cw(c712.23,596.24) 700.23,596.24 cw(c712.23,596.24) 712.23,608.24 cw(c712.23,596.24) 724.23,596.24 cw(c712.23,596.24)
  pour cut-out: 769.57,633.25 cw(c769.57,645.25) 757.57,645.25 cw(c769.57,645.25) 769.57,657.25 cw(c769.57,645.25) 781.57,645.25 cw(c769.57,645.25)
  pour cut-out: 591.3,128 cw(c591.3,140) 579.3,140 cw(c591.3,140) 591.3,152 cw(c591.3,140) 603.3,140 cw(c591.3,140)
  pour cut-out: 719.85,87.42 cw(c719.85,99.42) 707.85,99.42 cw(c719.85,99.42) 719.85,111.42 cw(c719.85,99.42) 731.85,99.42 cw(c719.85,99.42)
  pour cut-out: 700.81,308.3 cw(c700.81,320.3) 688.81,320.3 cw(c700.81,320.3) 700.81,332.3 cw(c700.81,320.3) 712.81,320.3 cw(c700.81,320.3)
  pour cut-out: 626,385 cw(c626,397) 614,397 cw(c626,397) 626,409 cw(c626,397) 638,397 cw(c626,397)
  pour cut-out: 565.13,425.16 cw(c565.13,437.16) 553.13,437.16 cw(c565.13,437.16) 565.13,449.16 cw(c565.13,437.16) 577.13,437.16 cw(c565.13,437.16)
  pour cut-out: 523.54,424.97 cw(c523.54,436.97) 511.54,436.97 cw(c523.54,436.97) 523.54,448.97 cw(c523.54,436.97) 535.54,436.97 cw(c523.54,436.97)
  pour cut-out: 545.73,376.65 cw(c545.73,388.65) 533.73,388.65 cw(c545.73,388.65) 545.73,400.65 cw(c545.73,388.65) 557.73,388.65 cw(c545.73,388.65)
  pour cut-out: 501.57,432.91 cw(c501.57,444.91) 489.57,444.91 cw(c501.57,444.91) 501.57,456.91 cw(c501.57,444.91) 513.57,444.91 cw(c501.57,444.91)
  pour cut-out: 461.93,344.95 cw(c461.93,356.95) 449.93,356.95 cw(c461.93,356.95) 461.93,368.95 cw(c461.93,356.95) 473.93,356.95 cw(c461.93,356.95)
  pour cut-out: 397.27,741.72 cw(c397.27,753.72) 385.27,753.72 cw(c397.27,753.72) 397.27,765.72 cw(c397.27,753.72) 409.27,753.72 cw(c397.27,753.72)
  pour cut-out: 397.27,867.71 cw(c397.27,879.71) 385.27,879.71 cw(c397.27,879.71) 397.27,891.71 cw(c397.27,879.71) 409.27,879.71 cw(c397.27,879.71)
  pour cut-out: 397.27,773.22 cw(c397.27,785.22) 385.27,785.22 cw(c397.27,785.22) 397.27,797.22 cw(c397.27,785.22) 409.27,785.22 cw(c397.27,785.22)
  pour cut-out: 428.76,773.22 cw(c428.76,785.22) 416.76,785.22 cw(c428.76,785.22) 428.76,797.22 cw(c428.76,785.22) 440.76,785.22 cw(c428.76,785.22)
  pour cut-out: 428.76,804.72 cw(c428.76,816.72) 416.76,816.72 cw(c428.76,816.72) 428.76,828.72 cw(c428.76,816.72) 440.76,816.72 cw(c428.76,816.72)
  pour cut-out: 428.76,867.71 cw(c428.76,879.71) 416.76,879.71 cw(c428.76,879.71) 428.76,891.71 cw(c428.76,879.71) 440.76,879.71 cw(c428.76,879.71)
  pour cut-out: 428.76,899.2 cw(c428.76,911.2) 416.76,911.2 cw(c428.76,911.2) 428.76,923.2 cw(c428.76,911.2) 440.76,911.2 cw(c428.76,911.2)
  pour cut-out: 397.27,899.2 cw(c397.27,911.2) 385.27,911.2 cw(c397.27,911.2) 397.27,923.2 cw(c397.27,911.2) 409.27,911.2 cw(c397.27,911.2)
  pour cut-out: 397.27,930.7 cw(c397.27,942.7) 385.27,942.7 cw(c397.27,942.7) 397.27,954.7 cw(c397.27,942.7) 409.27,942.7 cw(c397.27,942.7)
  pour cut-out: 207.31,581.91 cw(c207.31,593.91) 195.31,593.91 cw(c207.31,593.91) 207.31,605.91 cw(c207.31,593.91) 219.31,593.91 cw(c207.31,593.91)
  pour cut-out: -339.37,441.54 cw(c-339.37,453.54) -351.37,453.54 cw(c-339.37,453.54) -339.37,465.54 cw(c-339.37,453.54) -327.37,453.54 cw(c-339.37,453.54)
  pour cut-out: -374.36,311.85 cw(c-374.36,323.85) -386.36,323.85 cw(c-374.36,323.85) -374.36,335.85 cw(c-374.36,323.85) -362.36,323.85 cw(c-374.36,323.85)
  pour cut-out: -146.01,269.7 cw(c-146.01,281.7) -158.01,281.7 cw(c-146.01,281.7) -146.01,293.7 cw(c-146.01,281.7) -134.01,281.7 cw(c-146.01,281.7)
  pour cut-out: 333.39,458.53 cw(c333.39,470.53) 321.39,470.53 cw(c333.39,470.53) 333.39,482.53 cw(c333.39,470.53) 345.39,470.53 cw(c333.39,470.53)
  pour cut-out: 289.3,358.95 cw(c289.3,370.95) 277.3,370.95 cw(c289.3,370.95) 289.3,382.95 cw(c289.3,370.95) 301.3,370.95 cw(c289.3,370.95)
  text ".Layer_Name" at -147.27,-2480 h60
L04_GND2:
  text ".Layer_Name" at -77.19,-2480 h60
L07_GND3:
  text ".Layer_Name" at -59.66,-2515.05 h60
